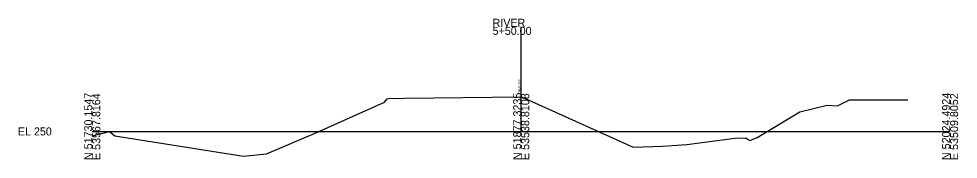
# Model space of a CAD drawing. Extents: x 5628 to 5956, y 92469 to 104012.
# Drawn here: x 5627.6 to 5956.2, y 94968.9 to 95017.9 of the extents above; entities that cross this region are included whole.
import ezdxf

# ---------------------------------------------------------------- set-up
doc = ezdxf.new("R2010")
doc.units = 0
for name, color, linetype in [('Level 10', 7, 'Continuous'), ('Level 60', 7, 'Continuous'), ('Level 63', 7, 'Continuous')]:
    doc.layers.add(name, color=color, linetype=linetype)

msp = doc.modelspace()

# ---------------------------------------------------------------- linework, layer by layer
at = {"layer": 'Level 60'}
for p, q in [((5755.59, 94988.85), (5756.46, 94990.04)), ((5756.46, 94990.04), (5757.52, 94990.2)), ((5757.52, 94990.2), (5759.42, 94990.05)), ((5759.42, 94990.05), (5762.57, 94990.2)), ((5762.57, 94990.2), (5803.44, 94990.74)), ((5803.44, 94990.74), (5842.5, 94973.08)), ((5914, 94987.5), (5918.17, 94989.61)), ((5918.17, 94989.61), (5928.1, 94989.62)), ((5928.1, 94989.62), (5932.14, 94989.69)), ((5932.14, 94989.69), (5938.57, 94989.64)), ((5731.25, 94977.98), (5755.59, 94988.85)), ((5900.81, 94985.5), (5910.37, 94987.72)), ((5910.37, 94987.72), (5914, 94987.5)), ((5885.88, 94976.48), (5900.81, 94985.5)), ((5653.34, 94977.02), (5659.34, 94978.59)), ((5659.34, 94978.59), (5661.19, 94977.01)), ((5661.19, 94977.01), (5706.17, 94969.94)), ((5714.3, 94970.74), (5731.25, 94977.98)), ((5861.32, 94974.07), (5878.11, 94976.28)), ((5878.11, 94976.28), (5881.92, 94976.37)), ((5881.92, 94976.37), (5882.44, 94975.84)), ((5884.46, 94975.88), (5885.88, 94976.48)), ((5842.5, 94973.08), (5852.71, 94973.42)), ((5852.71, 94973.42), (5861.32, 94974.07)), ((5882.44, 94975.84), (5883.29, 94975.45)), ((5883.29, 94975.45), (5884.46, 94975.88)), ((5706.17, 94969.94), (5714.3, 94970.74))]:
    msp.add_line(p, q, dxfattribs=at)
at = {"layer": 'Level 63'}
for p, q in [((5803.34, 94978.6), (5803.34, 95015.13)), ((5653.34, 94978.6), (5803.34, 94978.6)), ((5803.34, 94978.6), (5953.34, 94978.6))]:
    msp.add_line(p, q, dxfattribs=at)

# ---------------------------------------------------------------- texts
at = {"layer": 'Level 10'}
msp.add_text('256.07', height=1.2, rotation=90, dxfattribs=at).set_placement((5803.54, 94991.74))
at = {"layer": 'Level 63'}
for s, p in [('RIVER', (5793.34, 95015.13)), ('5+50.00', (5793.34, 95012.33)), ('EL 250', (5627.33, 94977.2))]:
    msp.add_text(s, height=2.8, dxfattribs=at).set_placement(p)
for s, p in [('N 51730.1547', (5653.34, 94968.6)), ('E 53567.8164', (5656.14, 94968.6)), ('N 51877.3235', (5803.34, 94968.6)), ('E 53538.8108', (5806.14, 94968.6)), ('N 52024.4924', (5953.34, 94968.6)), ('E 53509.8052', (5956.14, 94968.6))]:
    msp.add_text(s, height=2.8, rotation=90, dxfattribs=at).set_placement(p)

doc.saveas('drawing.dxf')
